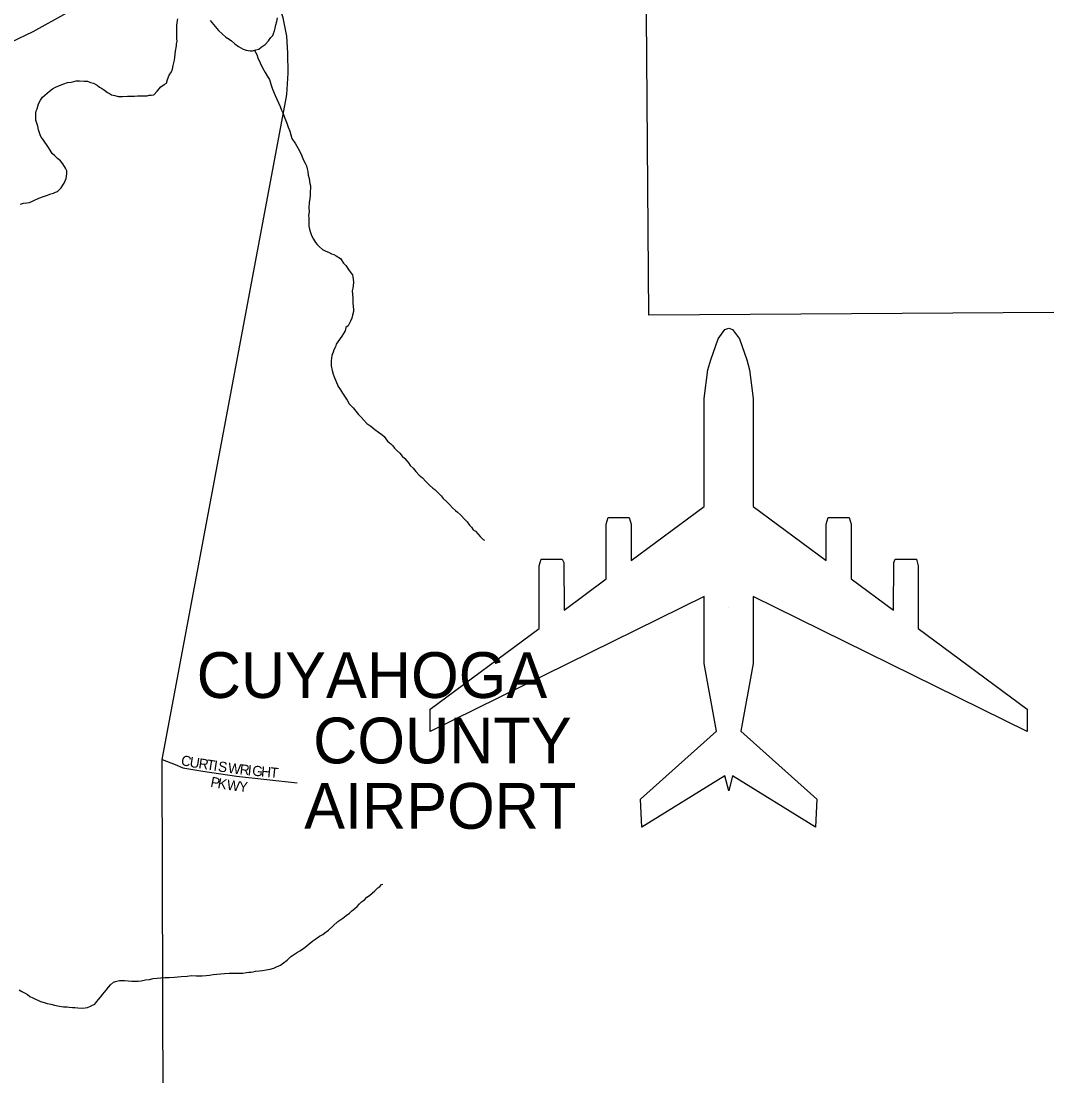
# Model space of a CAD drawing. Extents: x 2139079 to 2262683, y 1235796 to 1334992.
# Drawn here: x 2242458 to 2247498, y 1298455 to 1303635 of the extents above; entities that cross this region are included whole.
import ezdxf

# ---------------------------------------------------------------- set-up
doc = ezdxf.new("R2010")
doc.units = 0
for name, color, linetype in [('GM_X_Adjacent_County', 7, 'Continuous'), ('GM_X_Airport_Class_1', 7, 'Continuous'), ('GM_X_Airport_Location_Class_1', 7, 'Continuous'), ('GM_X_Airport_Text_Class_1', 7, 'Continuous'), ('GM_X_City_Street', 7, 'Continuous'), ('GM_X_City_Street_Text', 7, 'Continuous'), ('GM_X_Minor_River', 7, 'Continuous'), ('GM_X_State_Route', 7, 'Continuous'), ('GM_X_US_Route', 7, 'Continuous')]:
    doc.layers.add(name, color=color, linetype=linetype)

msp = doc.modelspace()

# ---------------------------------------------------------------- linework, layer by layer
at = {"layer": 'GM_X_Adjacent_County'}
msp.add_lwpolyline([(2252112.1, 1302234.6), (2248278.5, 1302209.7), (2246039.2, 1302195), (2245541.5, 1302191.8), (2245528.1, 1304087.2)], dxfattribs=at)
at = {"layer": 'GM_X_Airport_Class_1'}
for points in [[(2245934.8, 1299854.6), (2245916, 1299928.6), (2245507.9, 1299675.7), (2245502, 1299813.3), (2245874.6, 1300147.4), (2245814.5, 1300480), (2245814.5, 1300810.1), (2244468.2, 1300146.7), (2244468.2, 1300256.1), (2245003.6, 1300652.1), (2245003.6, 1300959.8), (2245013.1, 1300992.5), (2245116.7, 1300992.5), (2245123.9, 1300976.2), (2245126.1, 1300742.7), (2245332.9, 1300895.6), (2245332.9, 1301164.2), (2245342.4, 1301196.8), (2245446, 1301196.8), (2245455.4, 1301164.2), (2245455.4, 1300986.2), (2245814.5, 1301251.7), (2245814.5, 1301782.1), (2245832, 1301922.4), (2245846.6, 1301972.4), (2245882.6, 1302074.6), (2245915.8, 1302120), (2245934.8, 1302127.9)], [(2245934.8, 1302127.9), (2245953.7, 1302120), (2245986.9, 1302074.6), (2246022.9, 1301972.4), (2246037.5, 1301922.4), (2246055, 1301782.1), (2246055, 1301251.7), (2246414.1, 1300986.2), (2246414.1, 1301164.2), (2246423.5, 1301196.8), (2246527.1, 1301196.8), (2246536.6, 1301164.2), (2246536.6, 1300895.6), (2246743.4, 1300742.7), (2246745.6, 1300976.2), (2246752.8, 1300992.5), (2246856.4, 1300992.5), (2246865.9, 1300959.8), (2246865.9, 1300652.1), (2247401.3, 1300256.1), (2247401.3, 1300146.7), (2246055, 1300810.1), (2246055, 1300480), (2245994.9, 1300147.4), (2246367.5, 1299813.3), (2246361.6, 1299675.7), (2245953.6, 1299928.6), (2245934.8, 1299854.6)]]:
    msp.add_lwpolyline(points, dxfattribs=at)
at = {"layer": 'GM_X_Airport_Location_Class_1'}
msp.add_line((2245934.7, 1300756.1), (2245934.7, 1300756.1), dxfattribs=at)
at = {"layer": 'GM_X_City_Street'}
msp.add_lwpolyline([(2243151.2, 1300008.9), (2243214.6, 1299983.5), (2243252.6, 1299967.4), (2243350.4, 1299951.3), (2243516.2, 1299927.1), (2243813.9, 1299894.8)], dxfattribs=at)
at = {"layer": 'GM_X_Minor_River'}
for points in [[(2243223.9, 1303561.6), (2243223.7, 1303573.6), (2243223.6, 1303585.6), (2243223.4, 1303599.7), (2243223.3, 1303613.7), (2243225.1, 1303627.8), (2243228.9, 1303645.9)], [(2243387.3, 1303637.6), (2243427.9, 1303589.8), (2243446.1, 1303572), (2243464.3, 1303556.1), (2243480.5, 1303546.3), (2243492.6, 1303538.4), (2243508.8, 1303524.5), (2243527, 1303510.7), (2243537, 1303504.8), (2243549.2, 1303496.9), (2243563.2, 1303493), (2243573.3, 1303491.1), (2243583.3, 1303489.2), (2243595.3, 1303489.3), (2243611.3, 1303493.5), (2243625.3, 1303497.7), (2243637.2, 1303507.9), (2243657.1, 1303520.1), (2243672.9, 1303538.3), (2243684.7, 1303554.5), (2243694.7, 1303564.7), (2243698.5, 1303574.7), (2243702.4, 1303586.8), (2243706.3, 1303600.9), (2243710.1, 1303617), (2243713.9, 1303633.1), (2243717.7, 1303651.2)], [(2242455.8, 1302736.7), (2242469.7, 1302740.8), (2242485.7, 1302743), (2242499.7, 1302745.2), (2242517.7, 1302753.4), (2242545.6, 1302765.7), (2242567.5, 1302774), (2242587.5, 1302780.2), (2242603.5, 1302786.4), (2242617.4, 1302790.6), (2242627.4, 1302794.7), (2242637.4, 1302798.8), (2242655.2, 1302817.1), (2242663.1, 1302829.2), (2242669, 1302839.3), (2242674.9, 1302851.4), (2242678.8, 1302861.5), (2242680.6, 1302873.5), (2242682.5, 1302885.6), (2242682.3, 1302899.6), (2242676.2, 1302913.6), (2242663.9, 1302933.6), (2242651.7, 1302949.5), (2242637.6, 1302961.3), (2242623.4, 1302973.2), (2242611.2, 1302985.1), (2242601, 1303001.1), (2242592.9, 1303015), (2242582.7, 1303029), (2242574.5, 1303040.9), (2242564.4, 1303054.8), (2242556.3, 1303064.8), (2242552.1, 1303076.8), (2242548, 1303086.8), (2242543.8, 1303100.8), (2242539.6, 1303118.8), (2242535.4, 1303134.8), (2242531.3, 1303148.8), (2242531.1, 1303166.8), (2242530.9, 1303182.9), (2242532.8, 1303194.9), (2242536.6, 1303205), (2242544.4, 1303229.2), (2242554.2, 1303247.3), (2242564.1, 1303261.5), (2242585.9, 1303281.8), (2242597.8, 1303291.9), (2242611.7, 1303302.1), (2242627.6, 1303310.3), (2242647.6, 1303318.6), (2242667.5, 1303326.8), (2242685.5, 1303333), (2242703.5, 1303335.2), (2242717.4, 1303339.4), (2242729.4, 1303341.5), (2242745.5, 1303341.7), (2242767.5, 1303339.9), (2242783.6, 1303340.1), (2242799.7, 1303334.3), (2242813.7, 1303330.4), (2242831.9, 1303320.6), (2242844, 1303310.7), (2242858.1, 1303302.8), (2242868.2, 1303296.9), (2242882.4, 1303285), (2242892.4, 1303279.1), (2242902.5, 1303273.2), (2242918.6, 1303269.3), (2242934.7, 1303265.5), (2242956.7, 1303265.8), (2242980.7, 1303266), (2243014.8, 1303266.4), (2243030.8, 1303268.6), (2243040.8, 1303268.7), (2243056.8, 1303268.8), (2243066.9, 1303268.9), (2243076.9, 1303269.1), (2243086.9, 1303271.2), (2243096.9, 1303271.3), (2243110.9, 1303273.4), (2243126.7, 1303291.7), (2243144.5, 1303311.9), (2243160.4, 1303324.1), (2243172.4, 1303330.3), (2243178.2, 1303348.4), (2243185.9, 1303370.6), (2243197.8, 1303386.7), (2243201.6, 1303398.8), (2243205.4, 1303416.9), (2243211.2, 1303443.1), (2243216.7, 1303487.2), (2243222.4, 1303513.4), (2243222.3, 1303523.4), (2243224.1, 1303537.5), (2243224, 1303547.5), (2243223.9, 1303561.6)], [(2243603, 1303493.6), (2243615.6, 1303471.5), (2243621.7, 1303455.5), (2243632.1, 1303429.6), (2243644.3, 1303405.6), (2243656.6, 1303383.7), (2243668.9, 1303363.8), (2243679.1, 1303347.8), (2243685.3, 1303325.8), (2243693.6, 1303301.8), (2243706, 1303269.9), (2243730.6, 1303216), (2243736.8, 1303198), (2243745, 1303182), (2243751.2, 1303166.1), (2243757.4, 1303150.1), (2243763.6, 1303134.1), (2243769.8, 1303114.1), (2243778.1, 1303094.1), (2243788.5, 1303058.1), (2243806.8, 1303032.2), (2243819.1, 1303010.3), (2243829.3, 1302992.3), (2243837.5, 1302974.4), (2243843.7, 1302956.4), (2243854, 1302938.4), (2243860.1, 1302924.5), (2243864.3, 1302910.5), (2243866.5, 1302896.5), (2243868.7, 1302878.4), (2243872.9, 1302862.4), (2243877.1, 1302838.4), (2243879.3, 1302826.4), (2243879.4, 1302816.3), (2243877.6, 1302796.3), (2243877.8, 1302778.2), (2243876, 1302764.1), (2243874.2, 1302742.1), (2243872.5, 1302720), (2243872.7, 1302697.9), (2243870.9, 1302679.8), (2243871, 1302667.8), (2243871.2, 1302651.7), (2243871.4, 1302637.7), (2243871.5, 1302627.7), (2243875.7, 1302613.7), (2243877.8, 1302601.6), (2243881.9, 1302591.7), (2243886.1, 1302579.7), (2243894.2, 1302563.7), (2243904.4, 1302547.8), (2243912.6, 1302537.8), (2243924.7, 1302525.9), (2243938.9, 1302514), (2243955, 1302506.2), (2243969.1, 1302500.3), (2243983.2, 1302492.4), (2243995.3, 1302488.6), (2244005.4, 1302482.7), (2244027.6, 1302468.8), (2244041.8, 1302446.9), (2244054, 1302435), (2244060.1, 1302425.1), (2244066.2, 1302415.1), (2244078.4, 1302399.2), (2244086.5, 1302389.2), (2244088.7, 1302379.2), (2244088.8, 1302367.2), (2244091, 1302353.2), (2244089.2, 1302335.1), (2244087.3, 1302323), (2244085.4, 1302311), (2244085.6, 1302292.9), (2244087.8, 1302274.9), (2244088.1, 1302252.8), (2244090.3, 1302232.8), (2244090.5, 1302220.8), (2244090.6, 1302208.7), (2244086.8, 1302190.6), (2244082.9, 1302176.5), (2244077.1, 1302162.4), (2244065.3, 1302138.2), (2244053.4, 1302130.1), (2244049.6, 1302114), (2244033.9, 1302087.7), (2244014.1, 1302059.4), (2244006.2, 1302049.3), (2244002.4, 1302035.2), (2243994.5, 1302021.1), (2243990.7, 1302009), (2243984.8, 1301992.9), (2243981.1, 1301966.8), (2243981.4, 1301942.7), (2243985.7, 1301918.6), (2243991.9, 1301900.6), (2243996, 1301888.7), (2244016.6, 1301840.7), (2244026.8, 1301824.8), (2244037, 1301808.8), (2244047.2, 1301792.9), (2244059.4, 1301773)], [(2244059.4, 1301773), (2244069.7, 1301755), (2244079.8, 1301745.1), (2244089.9, 1301735.2), (2244102.1, 1301719.3), (2244116.3, 1301703.4), (2244128.5, 1301689.4), (2244142.7, 1301675.6), (2244156.9, 1301659.7), (2244177.1, 1301645.8), (2244195.3, 1301630), (2244213.5, 1301616.1), (2244229.6, 1301604.3), (2244241.8, 1301594.4), (2244258, 1301572.5), (2244274.2, 1301558.6), (2244284.4, 1301548.7), (2244292.5, 1301538.7), (2244302.6, 1301528.8), (2244318.8, 1301512.9), (2244331, 1301499), (2244343.2, 1301487.1), (2244353.3, 1301475.2), (2244361.4, 1301465.2), (2244369.6, 1301453.3), (2244383.8, 1301439.4), (2244398, 1301423.5), (2244414.2, 1301405.6), (2244430.4, 1301391.8), (2244446.6, 1301373.9), (2244464.8, 1301356), (2244481, 1301342.1), (2244491.1, 1301334.2), (2244501.3, 1301324.3), (2244511.4, 1301314.4), (2244521.5, 1301304.4), (2244531.7, 1301290.5), (2244547.9, 1301276.6), (2244562.1, 1301260.8), (2244578.3, 1301244.9), (2244592.5, 1301231), (2244602.6, 1301223.1), (2244616.7, 1301211.2), (2244639.1, 1301185.3), (2244649.2, 1301175.4), (2244661.4, 1301159.5), (2244671.5, 1301149.6), (2244679.7, 1301137.6), (2244689.8, 1301129.7), (2244701.9, 1301117.8), (2244714.1, 1301103.9), (2244728.3, 1301090), (2244734.4, 1301086)], [(2244083.7, 1299264.9), (2244097.6, 1299277.1), (2244109.5, 1299287.3), (2244121.4, 1299299.5), (2244131.3, 1299309.6), (2244145.2, 1299319.8), (2244157.1, 1299332), (2244169, 1299340.1), (2244182.9, 1299352.3), (2244196.8, 1299364.5), (2244210.7, 1299378.7), (2244220.6, 1299384.8), (2244228.5, 1299394.9), (2244234.5, 1299397)], [(2242449.2, 1298877.9), (2242461.3, 1298870.1), (2242475.4, 1298862.2), (2242489.5, 1298854.3), (2242501.7, 1298844.4), (2242515.8, 1298838.5), (2242554, 1298820.9), (2242572.1, 1298815.1), (2242586.2, 1298811.2), (2242604.3, 1298807.4), (2242622.4, 1298801.6), (2242646.4, 1298797.8), (2242666.5, 1298794), (2242684.6, 1298794.2), (2242694.6, 1298792.3), (2242710.6, 1298790.5), (2242722.7, 1298790.6), (2242736.7, 1298788.8), (2242754.8, 1298786.9), (2242772.8, 1298789.1), (2242784.8, 1298791.3), (2242798.7, 1298797.4), (2242808.7, 1298801.6), (2242820.6, 1298807.7), (2242830.5, 1298819.9), (2242838.4, 1298830), (2242848.3, 1298842.1), (2242860.2, 1298856.3), (2242868.1, 1298866.4), (2242876, 1298876.6), (2242887.8, 1298890.7), (2242897.7, 1298902.9), (2242911.6, 1298915.1), (2242921.6, 1298919.2), (2242941.6, 1298923.4), (2242953.6, 1298923.6), (2242965.6, 1298923.7), (2242983.6, 1298921.9), (2243001.7, 1298920.1), (2243017.7, 1298920.2), (2243033.7, 1298920.4), (2243047.7, 1298922.6), (2243069.7, 1298926.8), (2243089.7, 1298929.1), (2243107.7, 1298933.3), (2243163.8, 1298937.9), (2243185.8, 1298938.1), (2243211.8, 1298940.4), (2243243.9, 1298942.8), (2243273.9, 1298945.1), (2243295.9, 1298947.3), (2243318, 1298945.6), (2243348, 1298945.9), (2243368, 1298948.1), (2243384, 1298950.3), (2243402, 1298952.5), (2243420, 1298954.7), (2243438, 1298956.9), (2243458.1, 1298957.1), (2243480.1, 1298959.4), (2243506.1, 1298959.7), (2243530.2, 1298959.9), (2243548.2, 1298960.1), (2243566.2, 1298962.3), (2243576.2, 1298964.4), (2243586.2, 1298964.5), (2243598.2, 1298966.7), (2243610.2, 1298968.8), (2243630.2, 1298971.1), (2243644.2, 1298973.2), (2243662.2, 1298975.4), (2243682.2, 1298979.6), (2243700.2, 1298983.8), (2243712.2, 1298990), (2243732.1, 1298998.2), (2243748, 1299010.4), (2243765.9, 1299022.7), (2243781.7, 1299038.9), (2243801.6, 1299053.2), (2243815.5, 1299063.4), (2243827.5, 1299069.5), (2243841.4, 1299077.7), (2243853.3, 1299087.8), (2243873.2, 1299104.1), (2243891, 1299118.4), (2243906.9, 1299128.6), (2243924.8, 1299140.8), (2243940.8, 1299149), (2243950.7, 1299157.1), (2243968.6, 1299171.4), (2244014.2, 1299214), (2244038, 1299230.3), (2244055.9, 1299242.6), (2244071.8, 1299254.8), (2244083.7, 1299264.9)]]:
    msp.add_lwpolyline(points, dxfattribs=at)
at = {"layer": 'GM_X_State_Route'}
for points in [[(2243758.9, 1303247), (2243764.1, 1303274.9), (2243770.4, 1303379.2), (2243768.8, 1303477.3), (2243763.4, 1303561.4), (2243745.6, 1303650.6), (2243726.9, 1303707.1), (2243697.9, 1303768.8), (2243669.2, 1303810.4), (2243624.4, 1303859.7), (2243557.1, 1303934.7), (2243325.8, 1304133.3)], [(2243162.1, 1296011.9), (2243151.2, 1300008.9), (2243758.9, 1303247)]]:
    msp.add_lwpolyline(points, dxfattribs=at)
at = {"layer": 'GM_X_US_Route'}
msp.add_lwpolyline([(2242407.1, 1303532.6), (2242516.9, 1303584.9), (2242683.4, 1303675.8), (2242820, 1303758.2), (2242919, 1303820), (2243029.8, 1303891.9), (2243124.7, 1303957.7), (2243203.7, 1304021.1), (2243268.7, 1304078.3), (2243325.8, 1304133.3)], dxfattribs=at)

# ---------------------------------------------------------------- texts
at = {"layer": 'GM_X_Airport_Text_Class_1'}
for s, p in [('CUYAHOGA', (2243320.9, 1300310.9)), ('COUNTY', (2243892.9, 1299989.7)), ('AIRPORT', (2243848.9, 1299668.5))]:
    msp.add_text(s, height=225, rotation=0, dxfattribs=at).set_placement(p)
at = {"layer": 'GM_X_City_Street_Text'}
for s, rotation, p in [('C', 344.8918, (2243239.6, 1299984.1)), ('U', 351.251, (2243283.7, 1299972.6)), ('R', 351.482, (2243327.5, 1299965.8)), ('T', 351.4874, (2243366.6, 1299960)), ('I', 351.4865, (2243401.4, 1299954.8)), ('S', 351.4719, (2243423.2, 1299951.5)), ('W', 352.1884, (2243471.7, 1299944.2)), ('R', 354.135, (2243530.2, 1299936.2)), ('I', 354.2919, (2243569.8, 1299932.2)), ('G', 354.2851, (2243591.7, 1299930)), ('H', 354.2927, (2243635.5, 1299925.6)), ('T', 354.2813, (2243679.2, 1299921.2)), ('P', 349.1454, (2243385.8, 1299875.9)), ('K', 349.6808, (2243420.9, 1299869.2)), ('W', 351.7116, (2243466, 1299861)), ('Y', 355.1893, (2243525.9, 1299852.4))]:
    msp.add_text(s, height=50, rotation=rotation, dxfattribs=at).set_placement(p)

doc.saveas('drawing.dxf')
